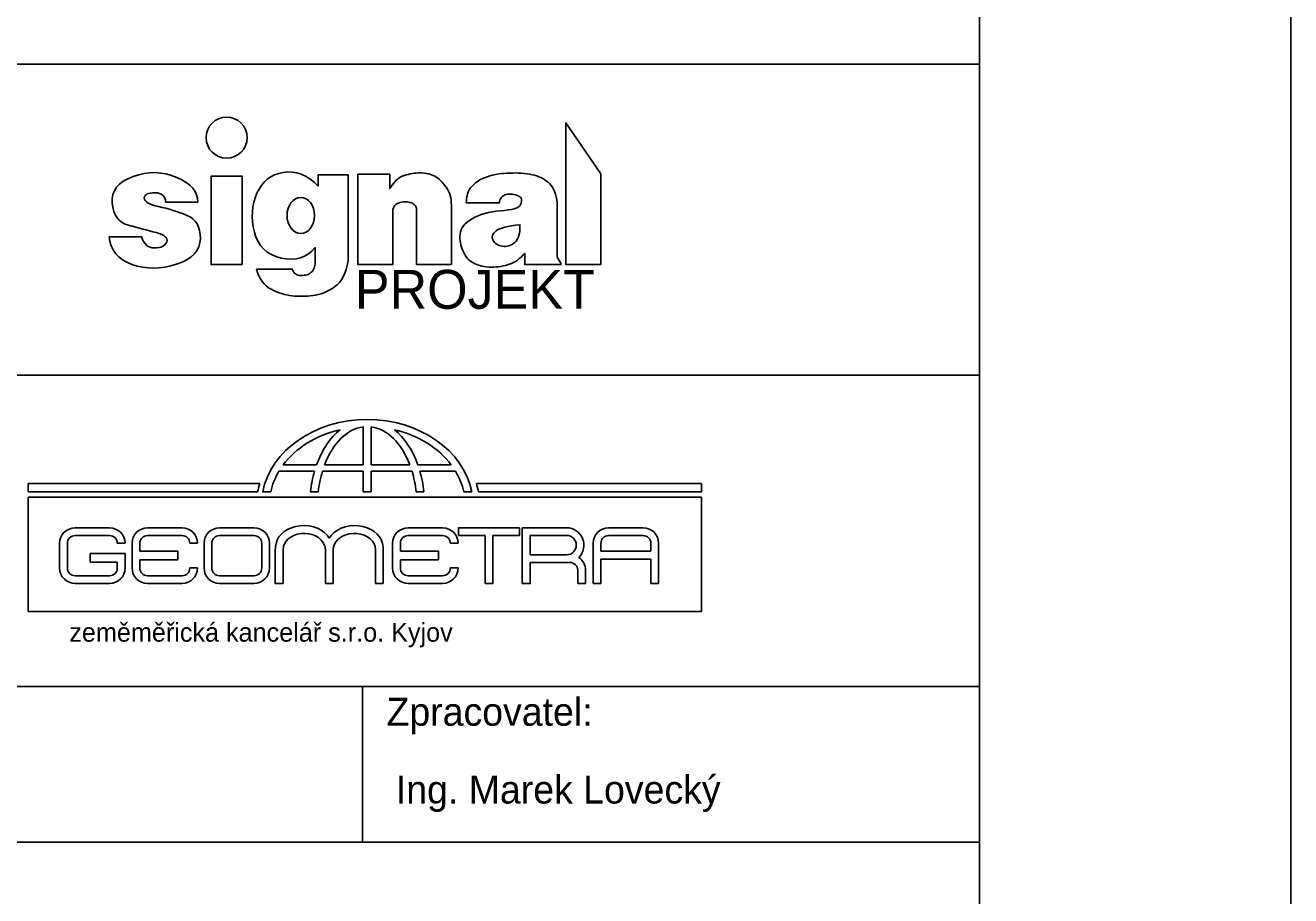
# Model space of a CAD drawing. Extents: x 3181 to 4881, y -3799 to -3355.
# Drawn here: x 4054.2 to 4135.6, y -3700 to -3644 of the extents above; entities that cross this region are included whole.
import ezdxf

# ---------------------------------------------------------------- set-up
doc = ezdxf.new("R2010")
doc.units = 0
for name, color, linetype in [('Default', 7, 'Continuous'), ('Vrstva 1', 7, 'Continuous'), ('Vrstva 11', 7, 'Continuous'), ('Vrstva 17', 7, 'Continuous'), ('Vrstva 6', 7, 'Continuous')]:
    doc.layers.add(name, color=color, linetype=linetype)

msp = doc.modelspace()

# ---------------------------------------------------------------- linework, layer by layer
at = {"layer": 'Default'}
msp.add_lwpolyline([(3925.563, -3798.543), (4135.563, -3798.543), (4135.563, -3501.543), (3925.563, -3501.543)], close=True, dxfattribs=at)
at = {"layer": 'Vrstva 1'}
msp.add_lwpolyline([(3945.563, -3521.543), (4115.563, -3521.543), (4115.563, -3781.543), (3945.563, -3781.543)], close=True, dxfattribs=at)
at = {"layer": 'Vrstva 11'}
for points in [[(4091.228, -3659.422), (4091.228, -3653.582), (4088.988, -3650.302), (4088.988, -3659.422), (4091.228, -3659.422)], [(4062.499, -3659.657), (4062.861, -3659.641), (4063.228, -3659.593), (4063.599, -3659.514), (4063.975, -3659.403), (4064.329, -3659.267), (4064.637, -3659.111), (4064.898, -3658.935), (4065.112, -3658.739), (4065.28, -3658.523), (4065.4, -3658.287), (4065.474, -3658.031), (4065.5, -3657.755), (4065.49, -3657.482), (4065.451, -3657.233), (4065.385, -3657.009), (4065.291, -3656.809), (4065.17, -3656.635), (4065.021, -3656.485), (4064.844, -3656.359), (4064.639, -3656.259), (4064.42, -3656.172), (4064.198, -3656.091), (4063.973, -3656.013), (4063.747, -3655.94), (4063.518, -3655.872), (4063.287, -3655.808), (4063.054, -3655.748), (4062.818, -3655.693), (4062.596, -3655.638), (4062.405, -3655.579), (4062.244, -3655.515), (4062.114, -3655.448), (4062.014, -3655.377), (4061.945, -3655.302), (4061.906, -3655.223), (4061.897, -3655.14), (4061.914, -3655.06), (4061.95, -3654.991), (4062.006, -3654.933), (4062.082, -3654.886), (4062.178, -3654.85), (4062.294, -3654.825), (4062.429, -3654.81), (4062.585, -3654.806), (4062.74, -3654.817), (4062.875, -3654.846), (4062.99, -3654.893), (4063.085, -3654.959), (4063.16, -3655.043), (4063.214, -3655.145), (4063.249, -3655.266), (4063.263, -3655.404), (4065.342, -3655.404), (4065.323, -3655.163), (4065.261, -3654.933), (4065.156, -3654.716), (4065.008, -3654.512), (4064.817, -3654.32), (4064.583, -3654.141), (4064.307, -3653.975), (4063.987, -3653.822), (4063.645, -3653.692), (4063.3, -3653.598), (4062.952, -3653.538), (4062.602, -3653.513), (4062.249, -3653.523), (4061.894, -3653.568), (4061.535, -3653.648), (4061.174, -3653.762), (4060.836, -3653.904), (4060.547, -3654.067), (4060.306, -3654.251), (4060.114, -3654.454), (4059.971, -3654.679), (4059.876, -3654.924), (4059.83, -3655.189), (4059.832, -3655.475), (4059.872, -3655.757), (4059.938, -3656.008), (4060.03, -3656.231), (4060.148, -3656.424), (4060.293, -3656.587), (4060.464, -3656.721), (4060.661, -3656.825), (4060.885, -3656.9), (4061.12, -3656.96), (4061.351, -3657.019), (4061.578, -3657.079), (4061.802, -3657.138), (4062.023, -3657.196), (4062.239, -3657.255), (4062.452, -3657.313), (4062.662, -3657.371), (4062.854, -3657.43), (4063.016, -3657.495), (4063.146, -3657.564), (4063.246, -3657.637), (4063.314, -3657.715), (4063.352, -3657.797), (4063.359, -3657.884), (4063.335, -3657.976), (4063.289, -3658.064), (4063.228, -3658.14), (4063.152, -3658.205), (4063.062, -3658.258), (4062.958, -3658.299), (4062.84, -3658.329), (4062.707, -3658.348), (4062.559, -3658.354), (4062.411, -3658.344), (4062.275, -3658.311), (4062.152, -3658.255), (4062.04, -3658.176), (4061.942, -3658.075), (4061.855, -3657.951), (4061.781, -3657.805), (4061.72, -3657.637), (4059.639, -3657.637), (4059.683, -3657.943), (4059.767, -3658.225), (4059.89, -3658.483), (4060.052, -3658.717), (4060.254, -3658.926), (4060.496, -3659.112), (4060.778, -3659.273), (4061.099, -3659.409), (4061.442, -3659.518), (4061.79, -3659.596), (4062.142, -3659.642), (4062.499, -3659.657)], [(4068.188, -3659.422), (4068.188, -3653.742), (4066.188, -3653.742), (4066.188, -3659.422), (4068.188, -3659.422)], [(4072.047, -3661.464), (4072.216, -3661.461), (4072.386, -3661.452), (4072.558, -3661.439), (4072.731, -3661.42), (4072.905, -3661.393), (4073.079, -3661.354), (4073.253, -3661.303), (4073.426, -3661.24), (4073.6, -3661.164), (4073.772, -3661.077), (4073.945, -3660.977), (4074.117, -3660.865), (4074.282, -3660.735), (4074.43, -3660.583), (4074.563, -3660.407), (4074.679, -3660.208), (4074.78, -3659.986), (4074.865, -3659.741), (4074.934, -3659.473), (4074.988, -3659.182), (4074.988, -3653.662), (4073.068, -3653.662), (4073.068, -3654.382), (4072.802, -3654.128), (4072.531, -3653.914), (4072.257, -3653.742), (4071.978, -3653.611), (4071.695, -3653.521), (4071.407, -3653.473), (4071.116, -3653.465), (4070.82, -3653.498), (4070.533, -3653.567), (4070.267, -3653.664), (4070.024, -3653.789), (4069.802, -3653.943), (4069.602, -3654.125), (4069.423, -3654.336), (4069.267, -3654.575), (4069.132, -3654.843), (4069.022, -3655.129), (4068.937, -3655.422), (4068.878, -3655.722), (4068.845, -3656.03), (4068.838, -3656.344), (4068.857, -3656.666), (4068.901, -3656.995), (4068.972, -3657.331), (4069.072, -3657.654), (4069.205, -3657.945), (4069.37, -3658.203), (4069.568, -3658.428), (4069.799, -3658.621), (4070.062, -3658.781), (4070.358, -3658.909), (4070.687, -3659.003), (4071.023, -3659.061), (4071.342, -3659.079), (4071.643, -3659.055), (4071.926, -3658.991), (4072.191, -3658.886), (4072.438, -3658.741), (4072.668, -3658.555), (4072.88, -3658.328), (4072.88, -3659.405), (4072.861, -3659.492), (4072.838, -3659.574), (4072.81, -3659.65), (4072.778, -3659.72), (4072.742, -3659.784), (4072.701, -3659.843), (4072.655, -3659.896), (4072.605, -3659.943), (4072.55, -3659.985), (4072.487, -3660.021), (4072.417, -3660.052), (4072.34, -3660.078), (4072.256, -3660.098), (4072.165, -3660.113), (4072.067, -3660.122), (4071.962, -3660.126), (4071.858, -3660.121), (4071.765, -3660.102), (4071.682, -3660.07), (4071.609, -3660.025), (4071.546, -3659.967), (4071.493, -3659.895), (4071.451, -3659.811), (4071.418, -3659.712), (4069.111, -3659.712), (4069.18, -3659.94), (4069.264, -3660.149), (4069.361, -3660.339), (4069.472, -3660.51), (4069.596, -3660.663), (4069.735, -3660.797), (4069.887, -3660.912), (4070.053, -3661.009), (4070.225, -3661.091), (4070.396, -3661.166), (4070.565, -3661.231), (4070.733, -3661.288), (4070.899, -3661.337), (4071.064, -3661.376), (4071.227, -3661.408), (4071.389, -3661.43), (4071.551, -3661.446), (4071.715, -3661.457), (4071.88, -3661.463), (4072.047, -3661.464)], [(4081.628, -3659.422), (4081.628, -3655.622), (4081.624, -3655.452), (4081.61, -3655.289), (4081.586, -3655.132), (4081.55, -3654.982), (4081.504, -3654.839), (4081.447, -3654.702), (4081.379, -3654.572), (4081.301, -3654.448), (4081.216, -3654.332), (4081.129, -3654.223), (4081.04, -3654.124), (4080.949, -3654.032), (4080.856, -3653.948), (4080.761, -3653.873), (4080.664, -3653.806), (4080.565, -3653.747), (4080.462, -3653.696), (4080.356, -3653.652), (4080.245, -3653.614), (4080.13, -3653.584), (4080.011, -3653.56), (4079.887, -3653.544), (4079.759, -3653.534), (4079.627, -3653.531), (4079.493, -3653.535), (4079.361, -3653.543), (4079.229, -3653.556), (4079.099, -3653.574), (4078.97, -3653.597), (4078.842, -3653.624), (4078.716, -3653.657), (4078.59, -3653.695), (4078.467, -3653.743), (4078.345, -3653.808), (4078.226, -3653.889), (4078.11, -3653.987), (4077.996, -3654.101), (4077.884, -3654.232), (4077.775, -3654.379), (4077.668, -3654.542), (4077.668, -3653.622), (4075.628, -3653.622), (4075.628, -3659.422), (4077.868, -3659.422), (4077.868, -3655.862), (4077.902, -3655.771), (4077.946, -3655.69), (4078.001, -3655.619), (4078.065, -3655.558), (4078.139, -3655.507), (4078.223, -3655.466), (4078.317, -3655.435), (4078.421, -3655.414), (4078.527, -3655.401), (4078.628, -3655.394), (4078.723, -3655.393), (4078.814, -3655.399), (4078.899, -3655.41), (4078.978, -3655.428), (4079.053, -3655.451), (4079.122, -3655.481), (4079.184, -3655.516), (4079.238, -3655.554), (4079.284, -3655.596), (4079.321, -3655.642), (4079.35, -3655.691), (4079.371, -3655.745), (4079.383, -3655.801), (4079.388, -3655.862), (4079.388, -3659.422), (4081.628, -3659.422)], [(4084.19, -3659.586), (4084.352, -3659.583), (4084.51, -3659.575), (4084.663, -3659.56), (4084.812, -3659.54), (4084.956, -3659.514), (4085.097, -3659.483), (4085.233, -3659.446), (4085.364, -3659.402), (4085.493, -3659.351), (4085.62, -3659.29), (4085.746, -3659.218), (4085.869, -3659.135), (4085.991, -3659.043), (4086.112, -3658.94), (4086.23, -3658.826), (4086.348, -3658.702), (4086.348, -3659.422), (4088.668, -3659.422), (4088.668, -3659.342), (4088.428, -3658.942), (4088.428, -3655.462), (4088.401, -3655.257), (4088.365, -3655.067), (4088.32, -3654.892), (4088.265, -3654.73), (4088.201, -3654.584), (4088.127, -3654.451), (4088.043, -3654.334), (4087.95, -3654.23), (4087.849, -3654.137), (4087.742, -3654.052), (4087.628, -3653.973), (4087.508, -3653.901), (4087.382, -3653.836), (4087.25, -3653.778), (4087.111, -3653.727), (4086.966, -3653.683), (4086.814, -3653.645), (4086.655, -3653.612), (4086.489, -3653.586), (4086.315, -3653.565), (4086.135, -3653.55), (4085.947, -3653.541), (4085.751, -3653.537), (4085.549, -3653.539), (4085.35, -3653.545), (4085.166, -3653.554), (4084.997, -3653.564), (4084.843, -3653.577), (4084.703, -3653.592), (4084.578, -3653.609), (4084.467, -3653.629), (4084.372, -3653.65), (4084.283, -3653.674), (4084.194, -3653.7), (4084.104, -3653.727), (4084.013, -3653.757), (4083.921, -3653.788), (4083.829, -3653.822), (4083.737, -3653.857), (4083.643, -3653.894), (4083.55, -3653.936), (4083.458, -3653.985), (4083.366, -3654.04), (4083.276, -3654.102), (4083.187, -3654.171), (4083.099, -3654.247), (4083.012, -3654.33), (4082.926, -3654.419), (4082.845, -3654.517), (4082.776, -3654.624), (4082.718, -3654.74), (4082.67, -3654.866), (4082.633, -3655.001), (4082.607, -3655.145), (4082.592, -3655.299), (4082.588, -3655.462), (4084.708, -3655.462), (4084.723, -3655.366), (4084.747, -3655.278), (4084.78, -3655.2), (4084.821, -3655.132), (4084.872, -3655.072), (4084.93, -3655.021), (4084.998, -3654.98), (4085.073, -3654.948), (4085.154, -3654.923), (4085.235, -3654.906), (4085.317, -3654.894), (4085.399, -3654.889), (4085.481, -3654.891), (4085.565, -3654.899), (4085.648, -3654.914), (4085.732, -3654.935), (4085.813, -3654.961), (4085.884, -3654.989), (4085.947, -3655.019), (4086, -3655.051), (4086.045, -3655.085), (4086.082, -3655.121), (4086.109, -3655.16), (4086.128, -3655.2), (4086.14, -3655.243), (4086.145, -3655.289), (4086.144, -3655.338), (4086.136, -3655.389), (4086.122, -3655.443), (4086.103, -3655.5), (4086.076, -3655.56), (4086.044, -3655.622), (4085.993, -3655.684), (4085.912, -3655.74), (4085.801, -3655.79), (4085.659, -3655.836), (4085.487, -3655.876), (4085.285, -3655.91), (4085.052, -3655.94), (4084.789, -3655.964), (4084.517, -3655.991), (4084.258, -3656.028), (4084.01, -3656.076), (4083.775, -3656.134), (4083.553, -3656.203), (4083.342, -3656.283), (4083.144, -3656.373), (4082.958, -3656.474), (4082.789, -3656.582), (4082.641, -3656.695), (4082.513, -3656.812), (4082.407, -3656.933), (4082.321, -3657.06), (4082.256, -3657.19), (4082.212, -3657.325), (4082.189, -3657.465), (4082.181, -3657.607), (4082.182, -3657.747), (4082.192, -3657.886), (4082.211, -3658.024), (4082.239, -3658.16), (4082.276, -3658.296), (4082.322, -3658.43), (4082.377, -3658.563), (4082.44, -3658.691), (4082.51, -3658.811), (4082.587, -3658.921), (4082.671, -3659.023), (4082.761, -3659.115), (4082.859, -3659.199), (4082.964, -3659.274), (4083.075, -3659.34), (4083.193, -3659.398), (4083.317, -3659.448), (4083.447, -3659.49), (4083.584, -3659.525), (4083.726, -3659.552), (4083.875, -3659.571), (4084.03, -3659.582), (4084.19, -3659.586)], [(4084.906, -3658.242), (4084.803, -3658.221), (4084.708, -3658.193), (4084.622, -3658.157), (4084.543, -3658.113), (4084.472, -3658.062), (4084.409, -3658.003), (4084.354, -3657.936), (4084.307, -3657.862), (4084.273, -3657.784), (4084.255, -3657.707), (4084.254, -3657.631), (4084.27, -3657.556), (4084.302, -3657.482), (4084.351, -3657.409), (4084.417, -3657.336), (4084.5, -3657.265), (4084.603, -3657.196), (4084.732, -3657.133), (4084.886, -3657.076), (4085.065, -3657.023), (4085.269, -3656.976), (4085.498, -3656.934), (4085.753, -3656.898), (4086.032, -3656.867), (4086.037, -3657.065), (4086.028, -3657.247), (4086.006, -3657.413), (4085.972, -3657.563), (4085.924, -3657.696), (4085.864, -3657.814), (4085.79, -3657.915), (4085.704, -3658), (4085.611, -3658.071), (4085.515, -3658.131), (4085.418, -3658.179), (4085.319, -3658.215), (4085.219, -3658.239), (4085.116, -3658.252), (4085.012, -3658.253), (4084.906, -3658.242)]]:
    msp.add_lwpolyline(points, dxfattribs=at)
msp.add_circle((4067.188, -3651.262), 1.32, dxfattribs=at)
msp.add_ellipse((4071.948, -3656.262), major_axis=(0, 1.16), ratio=0.758621, dxfattribs=at)
at = {"layer": 'Vrstva 17'}
for p, q in [((4075.958, -3669.856), (4075.958, -3672.301)), ((4076.465, -3672.301), (4076.465, -3669.853)), ((4070.545, -3672.713), (4072.832, -3672.713)), ((4072.965, -3672.301), (4070.82, -3672.301)), ((4073.342, -3672.713), (4075.958, -3672.713)), ((4075.958, -3672.301), (4073.482, -3672.301)), ((4075.958, -3672.713), (4075.958, -3674.033)), ((4078.96, -3672.301), (4076.465, -3672.301)), ((4076.465, -3674.033), (4076.465, -3672.713)), ((4076.465, -3672.713), (4079.099, -3672.713)), ((4081.622, -3672.301), (4079.477, -3672.301)), ((4079.609, -3672.713), (4081.897, -3672.713)), ((4069.314, -3673.502), (4054.433, -3673.502)), ((4054.433, -3673.502), (4054.433, -3674.033)), ((4097.712, -3673.502), (4083.233, -3673.502)), ((4097.712, -3674.033), (4097.712, -3673.502)), ((4097.71, -3674.378), (4054.427, -3674.378)), ((4054.427, -3674.378), (4054.427, -3681.716)), ((4054.433, -3674.033), (4069.176, -3674.033)), ((4069.502, -3674.033), (4070.019, -3674.033)), ((4072.575, -3674.033), (4073.075, -3674.033)), ((4075.958, -3674.033), (4076.465, -3674.033)), ((4079.366, -3674.033), (4079.866, -3674.033)), ((4082.423, -3674.033), (4082.94, -3674.033)), ((4083.371, -3674.033), (4097.712, -3674.033)), ((4097.71, -3681.716), (4097.71, -3674.378)), ((4057.452, -3676.344), (4059.663, -3676.344)), ((4059.663, -3676.842), (4057.452, -3676.842)), ((4062.108, -3676.344), (4064.319, -3676.344)), ((4064.319, -3676.842), (4062.108, -3676.842)), ((4066.732, -3676.344), (4068.943, -3676.344)), ((4068.943, -3676.842), (4066.732, -3676.842)), ((4078.851, -3676.344), (4081.061, -3676.344)), ((4081.061, -3676.842), (4078.851, -3676.842)), ((4083.794, -3679.925), (4083.794, -3676.83)), ((4084.297, -3676.83), (4084.297, -3679.925)), ((4086.188, -3676.344), (4089.032, -3676.344)), ((4089.032, -3676.832), (4086.692, -3676.832)), ((4086.692, -3676.832), (4086.692, -3678.082)), ((4091.736, -3676.344), (4093.947, -3676.344)), ((4093.947, -3676.842), (4091.736, -3676.842)), ((4056.454, -3678.928), (4056.454, -3677.341)), ((4056.953, -3677.341), (4056.953, -3678.928)), ((4060.66, -3677.341), (4060.162, -3677.341)), ((4061.11, -3678.928), (4061.11, -3677.341)), ((4061.609, -3677.341), (4061.609, -3677.852)), ((4065.317, -3677.341), (4064.818, -3677.341)), ((4065.734, -3678.928), (4065.734, -3677.341)), ((4066.233, -3677.341), (4066.233, -3678.928)), ((4069.442, -3678.928), (4069.442, -3677.341)), ((4069.941, -3677.341), (4069.941, -3678.928)), ((4070.313, -3679.925), (4070.313, -3677.741)), ((4070.814, -3677.741), (4070.814, -3679.925)), ((4073.533, -3679.925), (4073.533, -3677.741)), ((4074.033, -3677.741), (4074.033, -3679.925)), ((4076.752, -3679.925), (4076.752, -3677.741)), ((4077.253, -3677.741), (4077.253, -3679.925)), ((4077.853, -3678.928), (4077.853, -3677.341)), ((4078.352, -3677.341), (4078.352, -3677.852)), ((4082.059, -3677.341), (4081.56, -3677.341)), ((4090.738, -3679.925), (4090.738, -3677.341)), ((4091.237, -3677.341), (4091.237, -3677.85)), ((4094.446, -3677.85), (4094.446, -3677.341)), ((4094.945, -3677.341), (4094.945, -3679.925)), ((4058.427, -3678.549), (4058.427, -3678.005)), ((4058.427, -3678.005), (4060.66, -3678.005)), ((4060.162, -3678.549), (4058.427, -3678.549)), ((4060.162, -3678.928), (4060.162, -3678.549)), ((4060.66, -3678.005), (4060.66, -3678.928)), ((4061.609, -3677.852), (4064.052, -3677.852)), ((4064.052, -3678.397), (4061.609, -3678.397)), ((4061.609, -3678.397), (4061.609, -3678.928)), ((4064.052, -3677.852), (4064.052, -3678.397)), ((4078.352, -3677.852), (4080.795, -3677.852)), ((4080.795, -3678.397), (4078.352, -3678.397)), ((4078.352, -3678.397), (4078.352, -3678.928)), ((4080.795, -3677.852), (4080.795, -3678.397)), ((4086.692, -3678.082), (4089.032, -3678.082)), ((4089.032, -3678.571), (4086.692, -3678.571)), ((4089.247, -3678.575), (4089.032, -3678.571)), ((4091.237, -3677.85), (4094.446, -3677.85)), ((4094.446, -3678.354), (4091.237, -3678.354)), ((4091.237, -3678.354), (4091.237, -3679.925)), ((4094.446, -3679.925), (4094.446, -3678.354)), ((4064.818, -3678.928), (4065.317, -3678.928)), ((4081.56, -3678.928), (4082.059, -3678.928)), ((4089.746, -3679.925), (4089.746, -3679.074)), ((4090.244, -3679.074), (4090.244, -3679.925)), ((4057.452, -3679.427), (4059.663, -3679.427)), ((4059.663, -3679.925), (4057.452, -3679.925)), ((4062.108, -3679.427), (4064.319, -3679.427)), ((4064.319, -3679.925), (4062.108, -3679.925)), ((4066.732, -3679.427), (4068.943, -3679.427)), ((4068.943, -3679.925), (4066.732, -3679.925)), ((4070.814, -3679.925), (4070.313, -3679.925)), ((4074.033, -3679.925), (4073.533, -3679.925)), ((4077.253, -3679.925), (4076.752, -3679.925)), ((4078.851, -3679.427), (4081.061, -3679.427)), ((4081.061, -3679.925), (4078.851, -3679.925)), ((4084.297, -3679.925), (4083.794, -3679.925)), ((4090.244, -3679.925), (4089.746, -3679.925)), ((4091.237, -3679.925), (4090.738, -3679.925)), ((4094.945, -3679.925), (4094.446, -3679.925)), ((4054.427, -3681.716), (4097.71, -3681.716))]:
    msp.add_line(p, q, dxfattribs=at)
for points in [[(4083.794, -3676.83), (4082.096, -3676.83), (4082.096, -3676.344), (4086.009, -3676.344)], [(4086.009, -3676.344), (4086.009, -3676.83), (4084.297, -3676.83)], [(4086.692, -3678.571), (4086.692, -3679.925), (4086.188, -3679.925), (4086.188, -3676.344)]]:
    msp.add_lwpolyline(points, dxfattribs=at)
for centre, radius, start, end in [((4057.452, -3677.341), 0.998, 90, 180), ((4057.452, -3677.341), 0.499, 90, 180), ((4059.663, -3677.341), 0.998, 360, 90), ((4059.663, -3677.341), 0.499, 0, 90), ((4062.108, -3677.341), 0.998, 90, 180), ((4062.108, -3677.341), 0.499, 90, 180), ((4064.319, -3677.341), 0.998, 360, 90), ((4064.319, -3677.341), 0.499, 0, 90), ((4066.732, -3677.341), 0.998, 90, 180), ((4066.732, -3677.341), 0.499, 90, 180), ((4068.943, -3677.341), 0.998, 360, 90), ((4068.943, -3677.341), 0.499, 0, 90), ((4078.851, -3677.341), 0.998, 90, 180), ((4078.851, -3677.341), 0.499, 90, 180), ((4081.061, -3677.341), 0.998, 360, 90), ((4081.061, -3677.341), 0.499, 0, 90), ((4089.032, -3677.457), 1.114, 314.45734, 90), ((4089.032, -3677.457), 0.625, 270, 90), ((4091.736, -3677.341), 0.998, 90, 180), ((4091.736, -3677.341), 0.499, 90, 180), ((4093.947, -3677.341), 0.998, 360, 90), ((4093.947, -3677.341), 0.499, 0, 90), ((4072.25, -3677.791), 1.938, 166.96576, 178.52091), ((4072.579, -3677.805), 0.957, 3.86486, 22.41569), ((4075.266, -3677.862), 1.238, 162.61388, 174.3506), ((4075.315, -3677.791), 1.938, 1.47909, 13.03424), ((4089.247, -3679.074), 0.499, 0, 90), ((4089.247, -3679.074), 0.998, 360, 55.44734), ((4057.452, -3678.928), 0.998, 180, 270), ((4057.452, -3678.928), 0.499, 180, 270), ((4059.663, -3678.928), 0.998, 270, 0), ((4059.663, -3678.928), 0.499, 270, 0), ((4062.108, -3678.928), 0.998, 180, 270), ((4062.108, -3678.928), 0.499, 180, 270), ((4064.319, -3678.928), 0.998, 270, 0), ((4064.319, -3678.928), 0.499, 270, 0), ((4066.732, -3678.928), 0.998, 180, 270), ((4066.732, -3678.928), 0.499, 180, 270), ((4068.943, -3678.928), 0.998, 270, 0), ((4068.943, -3678.928), 0.499, 270, 0), ((4078.851, -3678.928), 0.998, 180, 270), ((4078.851, -3678.928), 0.499, 180, 270), ((4081.061, -3678.928), 0.998, 270, 0), ((4081.061, -3678.928), 0.499, 270, 0)]:
    msp.add_arc(centre, radius, start, end, dxfattribs=at)
for centre, major_axis, ratio, start_param, end_param in [((4076.221, -3674.906), (-6.804, 0), 0.811768, 3.300239, 6.124539), ((4076.221, -3674.906), (-6.296, 0), 0.804826, 4.992897, 5.743383), ((4076.221, -3674.906), (0, 5.524), 0.668443, 0.491666, 1.079789), ((4076.221, -3674.906), (0, 5.067), 0.630136, 0.08224, 1.030995), ((4076.221, -3674.906), (0, 5.067), 0.630136, 5.252191, 6.206521), ((4076.221, -3674.906), (0, 5.524), 0.668443, 5.203397, 5.79152), ((4076.221, -3674.906), (-6.296, 0), 0.804826, 3.681394, 4.431881), ((4076.221, -3674.906), (-6.296, 0), 0.804826, 5.835664, 6.110118), ((4076.221, -3674.906), (0, 5.524), 0.668443, 1.16256, 1.41215), ((4076.221, -3674.906), (0, 5.067), 0.630136, 1.123275, 1.397729), ((4076.221, -3674.906), (0, 5.067), 0.630136, 4.885456, 5.159911), ((4076.221, -3674.906), (0, 5.524), 0.668443, 4.871035, 5.120625), ((4076.221, -3674.906), (-6.296, 0), 0.804826, 3.31466, 3.589114), ((4075.895, -3674.906), (-6.804, 0), 0.811768, 6.026233, 6.124539), ((4076.653, -3674.906), (-6.804, 0), 0.811768, 3.300239, 3.398545), ((4072.142, -3677.585), (1.805, 0), 0.766187, 0.429647, 2.97338), ((4075.424, -3677.585), (-1.805, 0), 0.766187, 3.309805, 5.853538), ((4072.167, -3677.741), (1.354, 0), 0.766187, 0.29376, 3.141593), ((4075.398, -3677.741), (-1.354, 0), 0.766187, 3.141593, 6.041607)]:
    msp.add_ellipse(centre, major_axis=major_axis, ratio=ratio, start_param=start_param, end_param=end_param, dxfattribs=at)
at = {"layer": 'Vrstva 6'}
for p, q in [((3945.563, -3666.543), (4115.563, -3666.543)), ((3945.563, -3686.543), (4115.563, -3686.543)), ((4075.913, -3696.543), (4075.913, -3686.543))]:
    msp.add_line(p, q, dxfattribs=at)
msp.add_lwpolyline([(3945.563, -3646.543), (4115.563, -3646.543), (4115.563, -3696.543), (3945.563, -3696.543)], close=True, dxfattribs=at)

# ---------------------------------------------------------------- texts
at = {"layer": 'Vrstva 11'}
msp.add_text('PROJEKT', height=2.5, dxfattribs=at).set_placement((4075.428, -3662.265))
at = {"layer": 'Vrstva 17'}
msp.add_text('zeměměřická kancelář s.r.o. Kyjov', height=1.20984, dxfattribs=at).set_placement((4057.079, -3683.665))
at = {"layer": 'Vrstva 6'}
for s, p in [('Zpracovatel:', (4077.459, -3689.069)), ('Ing. Marek Lovecký', (4078.06, -3694.069))]:
    msp.add_text(s, height=1.8, dxfattribs=at).set_placement(p)

doc.saveas('drawing.dxf')
